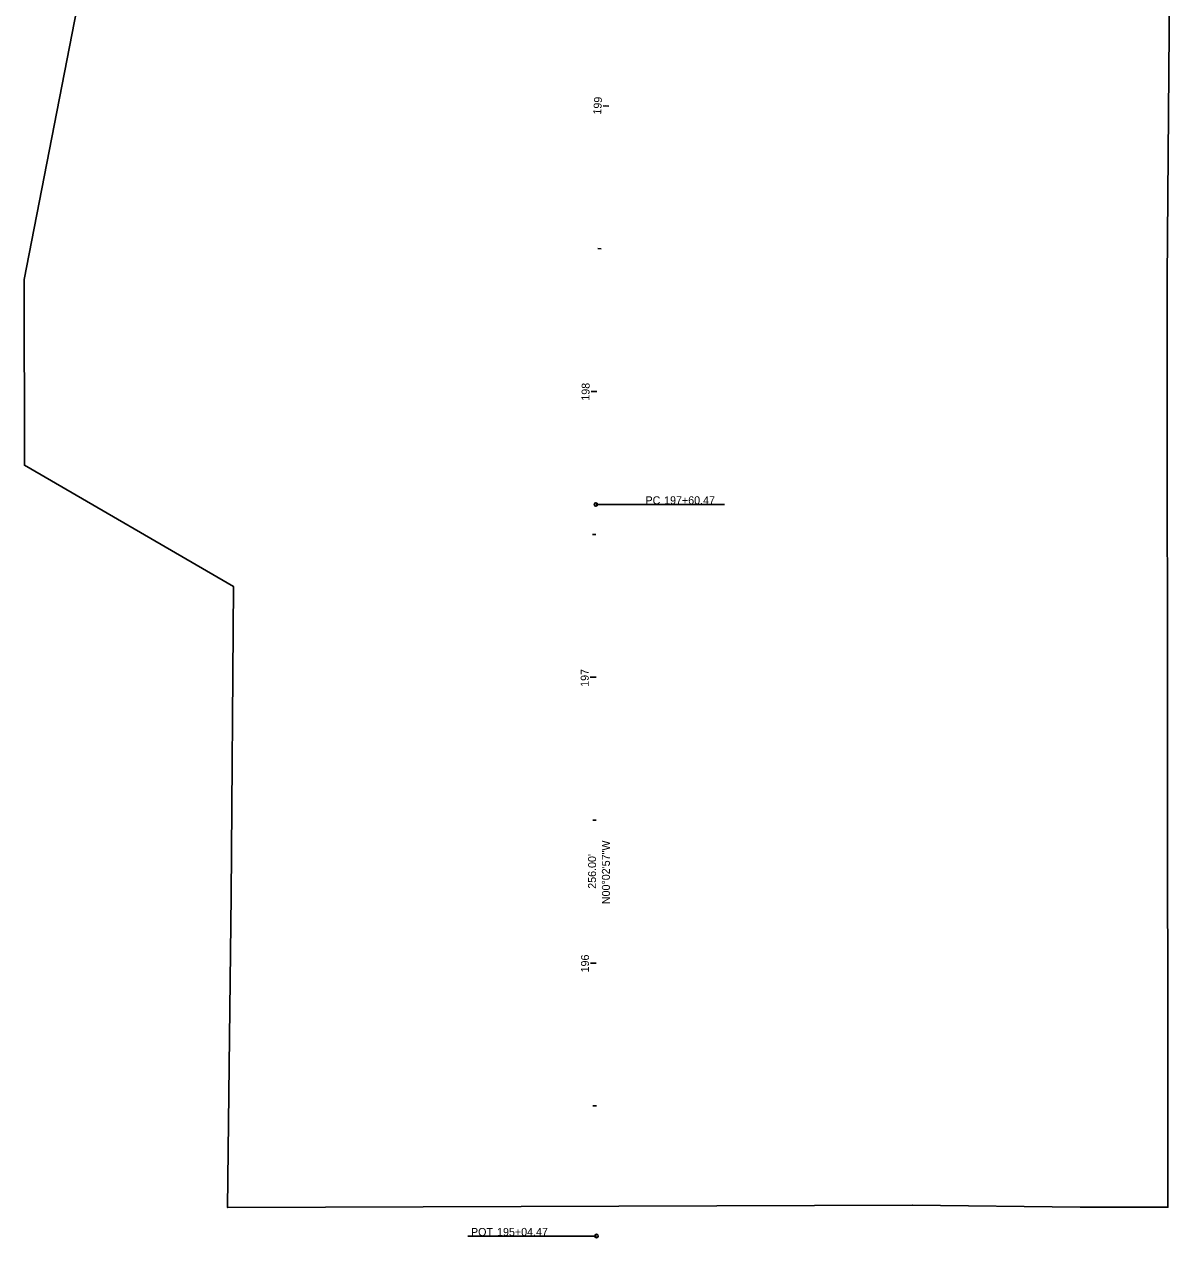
# Model space of a CAD drawing. Extents: x 1564517 to 1565226, y 635740 to 637455.
# Drawn here: x 1564587.2 to 1564988.1, y 635740 to 636164.7 of the extents above; entities that cross this region are included whole.
import ezdxf

# ---------------------------------------------------------------- set-up
doc = ezdxf.new("R2010")
doc.units = 0
for name, color, linetype in [('GE_P_Alignment_1000_Bearings', 7, 'Continuous'), ('GE_P_Alignment_1000_Cardinal_Points', 7, 'Continuous'), ('GE_P_Alignment_1000_Distances', 7, 'Continuous'), ('GE_P_Alignment_100_Bearings', 7, 'Continuous'), ('GE_P_Alignment_100_Cardinal_Points', 7, 'Continuous'), ('GE_P_Alignment_100_Distances', 7, 'Continuous'), ('GE_P_Alignment_100_Stations', 7, 'Continuous'), ('GE_P_Alignment_500_Bearings', 7, 'Continuous'), ('GE_P_Alignment_500_Cardinal_Points', 7, 'Continuous'), ('GE_P_Alignment_500_Distances', 7, 'Continuous'), ('GE_P_Alignment_500_Stations', 7, 'Continuous'), ('SH_Named_Boundary', 7, 'Continuous')]:
    doc.layers.add(name, color=color, linetype=linetype)

msp = doc.modelspace()

# ---------------------------------------------------------------- linework, layer by layer
at = {"layer": 'GE_P_Alignment_1000_Cardinal_Points'}
for p, q in [((1564787.24, 635996.63), (1564832.24, 635996.67)), ((1564787.45, 635740.63), (1564742.45, 635740.59))]:
    msp.add_line(p, q, dxfattribs=at)
for centre in [(1564787.24, 635996.63), (1564787.45, 635740.63)]:
    msp.add_circle(centre, 0.6, dxfattribs=at)
at = {"layer": 'GE_P_Alignment_100_Cardinal_Points'}
for p, q in [((1564787.24, 635996.63), (1564832.24, 635996.67)), ((1564787.45, 635740.63), (1564742.45, 635740.59))]:
    msp.add_line(p, q, dxfattribs=at)
for centre in [(1564787.24, 635996.63), (1564787.45, 635740.63)]:
    msp.add_circle(centre, 0.6, dxfattribs=at)
at = {"layer": 'GE_P_Alignment_100_Stations'}
for p, q in [((1564791.8, 636136.06), (1564789.81, 636136.19)), ((1564789.09, 636086.14), (1564787.89, 636086.19)), ((1564787.58, 636036.16), (1564785.58, 636036.2)), ((1564787.24, 635986.16), (1564786.04, 635986.16)), ((1564787.29, 635936.16), (1564785.29, 635936.16)), ((1564787.33, 635886.16), (1564786.13, 635886.16)), ((1564787.37, 635836.16), (1564785.37, 635836.16)), ((1564787.42, 635786.16), (1564786.22, 635786.16))]:
    msp.add_line(p, q, dxfattribs=at)
at = {"layer": 'GE_P_Alignment_500_Cardinal_Points'}
for p, q in [((1564787.24, 635996.63), (1564832.24, 635996.67)), ((1564787.45, 635740.63), (1564742.45, 635740.59))]:
    msp.add_line(p, q, dxfattribs=at)
for centre in [(1564787.24, 635996.63), (1564787.45, 635740.63)]:
    msp.add_circle(centre, 0.6, dxfattribs=at)
at = {"layer": 'GE_P_Alignment_500_Stations'}
for p, q in [((1564791.8, 636136.06), (1564790.61, 636136.14)), ((1564787.58, 636036.16), (1564786.38, 636036.18)), ((1564787.29, 635936.16), (1564786.09, 635936.16)), ((1564787.37, 635836.16), (1564786.17, 635836.16))]:
    msp.add_line(p, q, dxfattribs=at)
at = {"layer": 'SH_Named_Boundary'}
msp.add_lwpolyline([(1564658.34, 635750.59), (1564898, 635751.43), (1564898, 635751.43), (1564898, 635751.43), (1564956.75, 635750.68), (1564987.45, 635750.7), (1564987.39, 635815.7), (1564987.33, 635880.7), (1564987.28, 635945.7), (1564987.22, 636010.7), (1564987.17, 636075.7), (1564988.09, 636191.25), (1564617.12, 636229.41), (1564587.17, 636075.36), (1564587.22, 636010.36), (1564660.39, 635967.97), (1564659.6, 635859.64), (1564658.34, 635750.59), (1564658.34, 635750.59)], close=True, dxfattribs=at)

# ---------------------------------------------------------------- texts
at = {"layer": 'GE_P_Alignment_1000_Bearings'}
msp.add_text('N00°02\'57"W', height=2.8, rotation=90.0491, dxfattribs=at).set_placement((1564792.16, 635856.77))
at = {"layer": 'GE_P_Alignment_1000_Cardinal_Points'}
for s, p in [('PC', (1564804.6, 635996.69)), ('197+60.47', (1564811.12, 635996.7)), ('POT', (1564743.52, 635740.64)), ('195+04.47', (1564752.65, 635740.65))]:
    msp.add_text(s, height=2.8, rotation=0.0491, dxfattribs=at).set_placement(p)
at = {"layer": 'GE_P_Alignment_1000_Distances'}
msp.add_text("256.00'", height=2.8, rotation=90.0491, dxfattribs=at).set_placement((1564787.3, 635862.15))
at = {"layer": 'GE_P_Alignment_100_Bearings'}
msp.add_text('N00°02\'57"W', height=2.8, rotation=90.0491, dxfattribs=at).set_placement((1564792.16, 635856.77))
at = {"layer": 'GE_P_Alignment_100_Cardinal_Points'}
for s, p in [('PC', (1564804.6, 635996.69)), ('197+60.47', (1564811.12, 635996.7)), ('POT', (1564743.52, 635740.64)), ('195+04.47', (1564752.65, 635740.65))]:
    msp.add_text(s, height=2.8, rotation=0.0491, dxfattribs=at).set_placement(p)
at = {"layer": 'GE_P_Alignment_100_Distances'}
msp.add_text("256.00'", height=2.8, rotation=90.0491, dxfattribs=at).set_placement((1564787.3, 635862.15))
at = {"layer": 'GE_P_Alignment_100_Stations'}
for s, rotation, p in [('199', 86.1971, (1564789.05, 636132.99)), ('198', 88.9578, (1564784.97, 636032.93)), ('197', 90.0491, (1564784.74, 635932.82)), ('196', 90.0491, (1564784.83, 635832.88))]:
    msp.add_text(s, height=2.8, rotation=rotation, dxfattribs=at).set_placement(p)
at = {"layer": 'GE_P_Alignment_500_Bearings'}
msp.add_text('N00°02\'57"W', height=2.8, rotation=90.0491, dxfattribs=at).set_placement((1564792.16, 635856.77))
at = {"layer": 'GE_P_Alignment_500_Cardinal_Points'}
for s, p in [('PC', (1564804.6, 635996.69)), ('197+60.47', (1564811.12, 635996.7)), ('POT', (1564743.52, 635740.64)), ('195+04.47', (1564752.65, 635740.65))]:
    msp.add_text(s, height=2.8, rotation=0.0491, dxfattribs=at).set_placement(p)
at = {"layer": 'GE_P_Alignment_500_Distances'}
msp.add_text("256.00'", height=2.8, rotation=90.0491, dxfattribs=at).set_placement((1564787.3, 635862.15))

doc.saveas('drawing.dxf')
